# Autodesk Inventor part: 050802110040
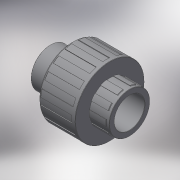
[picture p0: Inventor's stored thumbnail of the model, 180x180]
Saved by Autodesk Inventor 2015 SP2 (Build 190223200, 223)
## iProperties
Created: 2017-10
Part Number: 050802110040
Material: Generic
Description: PLASSON UNION+O RING THR-CEM 110-4
Document SubType Name: Modeling
Designer: KIM
Density: 1 g/cm^3
Appearance: Default
Author: KIM
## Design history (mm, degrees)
derived "050802.ipt"
feature "Solid1::050802.ipt"
tag "TaggingFeature1"
body "Solid1"
other parameters: "d0" = 145, "d4" = 110.072, "d5" = 132, "d6" = 137.5, "d7" = 140.8, "d8" = 151, "d9" = 61, "d11" = 93.5, "d12" = 104.5, "d15" = 45.75, "d16" = 39.6, "d17" = 4, "d19" = 147.98, "d20" = 6.1, "d21" = 4.53, "d25" = 15.1, "d26" = 7.55, "d27" = 56.835, "d28" = 0, "d32" = 15.1, "d33" = 7.55, "d35" = 0, "d39" = 1.1, "d45" = 1.65, "d49" = 360 deg, "d51" = 1.51, "d55" = 360 deg, "E_" = 151, "H_" = 39, "l_" = 61, "Z_" = 11, "G_" = 110.072, "d13" = 44, "d24" = 63.15, "d40" = 1.65, "d44" = 1.51
